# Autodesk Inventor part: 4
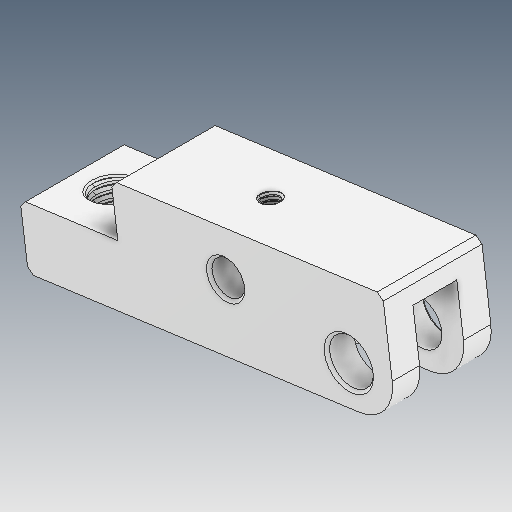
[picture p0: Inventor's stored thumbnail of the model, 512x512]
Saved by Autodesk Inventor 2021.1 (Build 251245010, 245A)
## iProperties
Created: 2021-06
Part Number: 4
Material: Ogólny
Document SubType Name: Modeling
Designer: user
Density: 1 g/cm^3
Appearance: Domyślna
Author: user
Revision Number: ÈÎºÎ
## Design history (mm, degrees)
feature "ÊäÈë1"
node "Bryła1"
